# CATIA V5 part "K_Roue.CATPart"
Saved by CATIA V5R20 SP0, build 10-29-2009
Part number: Roue
Publications: "diametre_interieure_roue", "diametre_exterieure_roue", "epaisseur_roue_interieure", "diamètre_essieu"
Bounding box of the stored display mesh (mm): x -151.186 to 75.186, y 82.147 to 282.11, z -294.427 to -94.482
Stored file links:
  G:\Khaled_CFAO_2011\ST2M\ST2M_GR2\plakomicki\Khaled\CAD_ThinkMOTION\K_Roue.CATPart
  G:\Khaled_CFAO_2011\ST2M\ST2M_GR2\plakomicki\Khaled\CAD_ThinkMOTION\K_Jambe.CATProduct
  G:\Khaled_CFAO_2011\ST2M\ST2M_GR2\plakomicki\Khaled\CAD_ThinkMOTION\K_SquelPaire_Roue.CATPart
  G:\Khaled_CFAO_2011\ST2M\ST2M_GR2\plakomicki\Khaled\plakomicki\Squelette_balancier.CATPart
  G:\Khaled_CFAO_2011\ST2M\ST2M_GR2\plakomicki\Khaled\plakomicki\Structure.CATPart
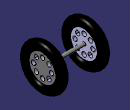
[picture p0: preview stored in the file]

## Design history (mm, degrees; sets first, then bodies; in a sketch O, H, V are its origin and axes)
Parameters
  diametre_interieure_roue = 120 mm
  diametre_exterieure_roue = 200 mm
  epaisseur_roue_interieure = 15 mm
  `diamètre_essieu` = 15 mm
External parameters (linked from other documents)
  External.entraxe_roue = 200 mm
Set1
  Plane1: linked copy from another document
  DatumPoint1: linked copy from another document
  Plane2: linked copy from another document
  Plane3: linked copy from another document
  Line1: linked copy from another document
  Plane4: linked copy from another document
  Point1: linked copy from another document
  Point2: linked copy from another document
Body1 (main body)
  Sketch1 on Plane1, origin (62, 0, 0), H (0, 1, 0), V (0, 0, 1)
    circle A1 centre (182.1285, -194.4544) radius 7.5
    point P1 (182.1285, -194.4544)
    reference projected point E1 (182.1285, -194.4544) from vertex of DatumPoint1
    radius A1 = 7.5 {= `diamètre_essieu` /2}
    coincidence: E1 P1
  Pad1: profile Sketch1, direction (1, 0, 0), up to Plane2
  Sketch2 on Plane3, origin (0, 439.3393, -125.5349), H (-1, 0, 0), V (0, 0.9659, 0.2588)
    point P1 (-54.5, -166.2843)
    line L1 (-62, -266.2843) -> (-62, -206.2843)
    point P2 (-62, -266.2843)
    point P3 (-62, -206.2843)
    reference projected point E1 (-62, -266.2843) from DatumPoint1
    point P4 (-47, -206.2843)
    line L2 (-47, -206.2843) -> (-47, -266.2843)
    line L3 (-62, -266.2843) -> (-47, -266.2843)
    arc A1 centre (-54.5, -186.9874) radius 20.7031 from (-62, -206.2843) to (-47, -206.2843) cw
    distance L1 L2 = 15 {= epaisseur_roue_interieure}
    distance P1 L2 = 7.5 {= epaisseur_roue_interieure /2}
    distance P1 L3 = 100 {= diametre_exterieure_roue /2}
    distance P4 L3 = 60 {= diametre_interieure_roue /2}
    distance P3 L3 = 60 {= diametre_interieure_roue /2}
    vertical: L1 V, L2 V
    coincidence: P2 E1, A1 P1
    horizontal: L3 H
  Shaft1: profile Sketch2, axis Line1, angle 360
  Sketch3 on face of Shaft1, origin (62, 0, 0), H (0, 1, 0), V (0, 0, 1)
    circle A1 centre (182.1285, -154.4544) radius 10
    point P1 (182.1285, -154.4544)
    reference projected point E1 (182.1285, -194.4544) from Point1
    reference projected point E2 (182.1285, -194.4544) from Point1
    radius A1 = 10 {= diametre_interieure_roue /12}
    distance P1 E1 = 40 {= diametre_interieure_roue /3}
    distance P1 E2 H = 0
  Pocket1: profile Sketch3, direction (-1, 0, 0), up to face of Shaft1 from Sketch2.L2
  CircPattern1: of Pocket1, instances 8, angular step 45, axis from Line1
  Mirror1: of Shaft1, Sketch2, about Plane4
  Sketch4 on face of Mirror1, origin (-138, 0, 0), H (0, -1, 0), V (0, 0, 1)
    circle A1 centre (-182.1285, -154.4544) radius 10
    point P1 (-182.1285, -154.4544)
    reference projected point E1 (-182.1285, -194.4544) from Point1
    reference projected point E2 (-182.1285, -194.4544) from Point2
    radius A1 = 10 {= diametre_interieure_roue /12}
    distance P1 E1 H = 0
    distance E2 P1 = 40 {= diametre_interieure_roue /3}
  Pocket2: profile Sketch4, direction (1, 0, 0), up to face of Mirror1
  CircPattern2: of Pocket2, instances 8, angular step 45, axis from Line1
